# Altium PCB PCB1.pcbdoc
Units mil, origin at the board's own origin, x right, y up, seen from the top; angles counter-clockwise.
Board outline 797.75 x 971.83 mil, 2 copper layers (Top Layer, Bottom Layer); 1 components, 0 nets, 3 pads, 0 vias.
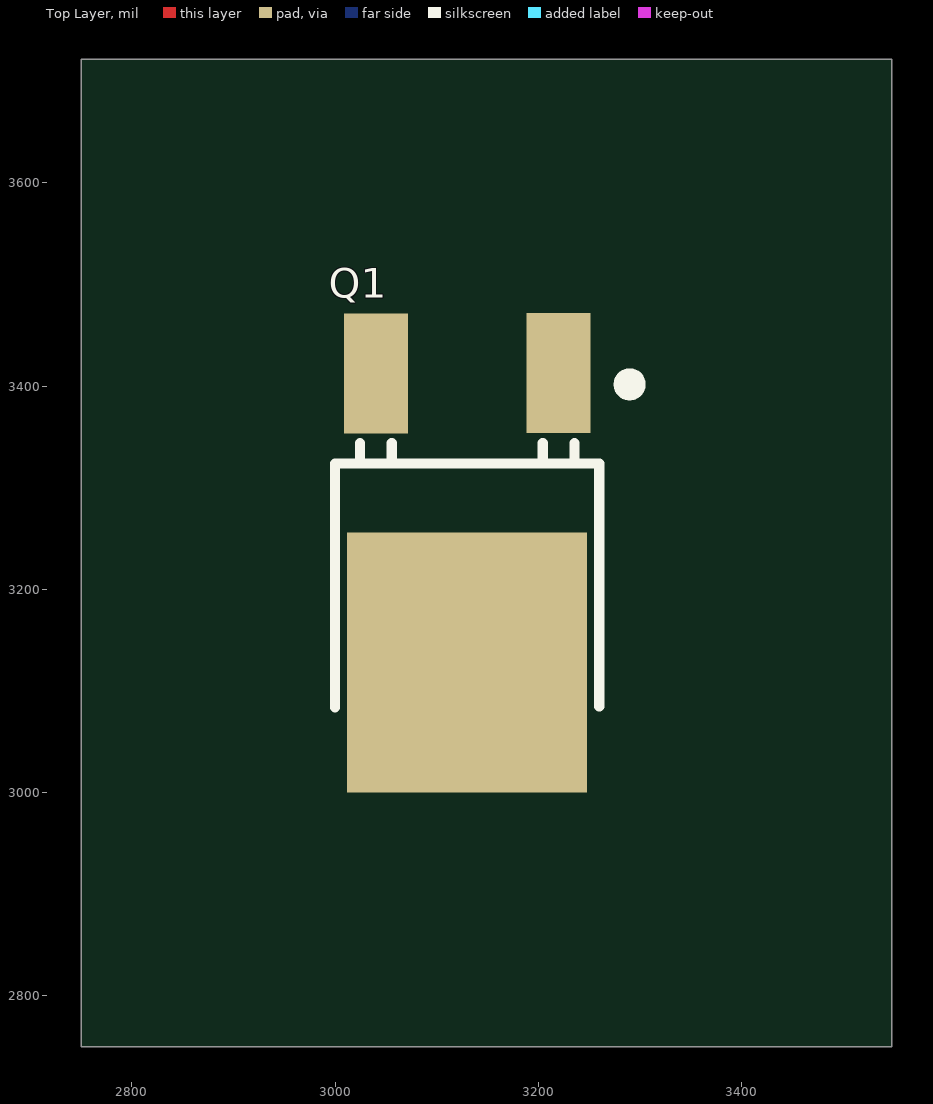
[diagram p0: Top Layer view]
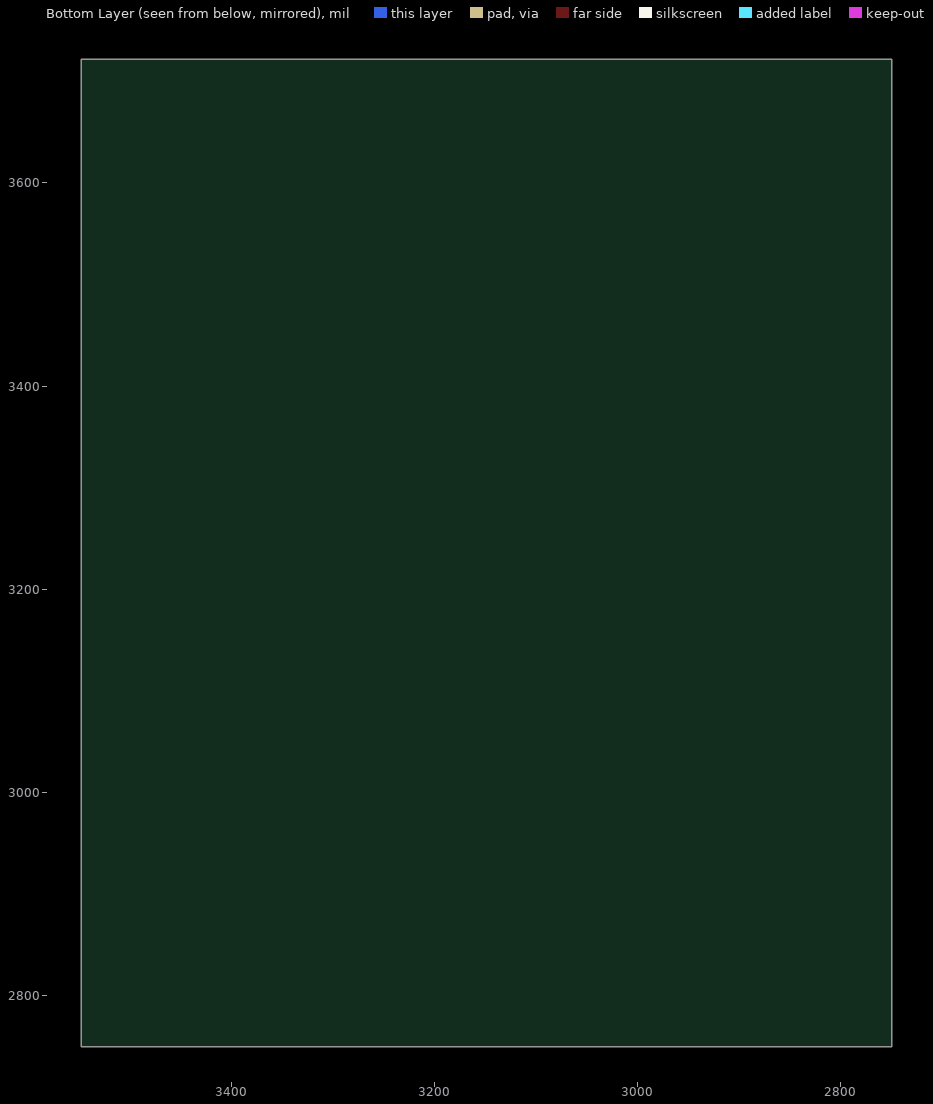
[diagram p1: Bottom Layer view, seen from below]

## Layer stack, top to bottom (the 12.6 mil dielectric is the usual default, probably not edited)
Top Layer: signal copper (thickness not stored)
Dielectric: dielectric 12.6, FR-4, Dk 4.8
Bottom Layer: signal copper (thickness not stored)

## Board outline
3547.75,2750 2750,2750 2750,3721.83 3547.75,3721.83

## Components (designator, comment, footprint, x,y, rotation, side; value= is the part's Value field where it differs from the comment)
Q1 "IRFR220NTRPBF" TO-252-2_L6.6-W6.1-P4.57-LS9.9-TR-CW 3130,3270.36 r0 top

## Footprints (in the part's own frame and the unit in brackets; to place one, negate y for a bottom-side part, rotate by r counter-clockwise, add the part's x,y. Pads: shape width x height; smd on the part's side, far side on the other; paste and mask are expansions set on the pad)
TO-252-2_L6.6-W6.1-P4.57-LS9.9-TR-CW [mm]
  rect 1.6x3 smd: 1(2.285,3.617) 3(-2.285,3.611)
  rect 6x6.5 smd: 2(0,-3.617)
  silkscreen extent -3.3,-4.74 4.26,3.54

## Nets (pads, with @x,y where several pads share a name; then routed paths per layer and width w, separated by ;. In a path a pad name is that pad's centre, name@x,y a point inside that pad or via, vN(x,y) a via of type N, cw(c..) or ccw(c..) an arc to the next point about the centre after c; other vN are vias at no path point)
pads on no net: Q1.1 Q1.2 Q1.3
